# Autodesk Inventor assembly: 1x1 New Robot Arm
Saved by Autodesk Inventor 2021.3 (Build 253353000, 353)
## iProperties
Created: 2022-04
Part Number: 1x1 New Robot Arm
Document SubType Name: Assembly
Designer: Administrator
Title: 1x1 New Robot Arm v1
Author: Administrator
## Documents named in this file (2)
- c:\worker\convert-fusion-r02\tmp\job-1\85\output\files\37cd6712-e1fe-4c12-b36f-598d072b34ae\da89a58c-ebd7-4bc3-87dc-50b852e85cb0.iam
- c:\worker\convert-fusion-r02\tmp\job-1\85\output\files\37cd6712-e1fe-4c12-b36f-598d072b34ae\Component1.ipt
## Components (1 placed, 1 different names)
1. Component1:1
